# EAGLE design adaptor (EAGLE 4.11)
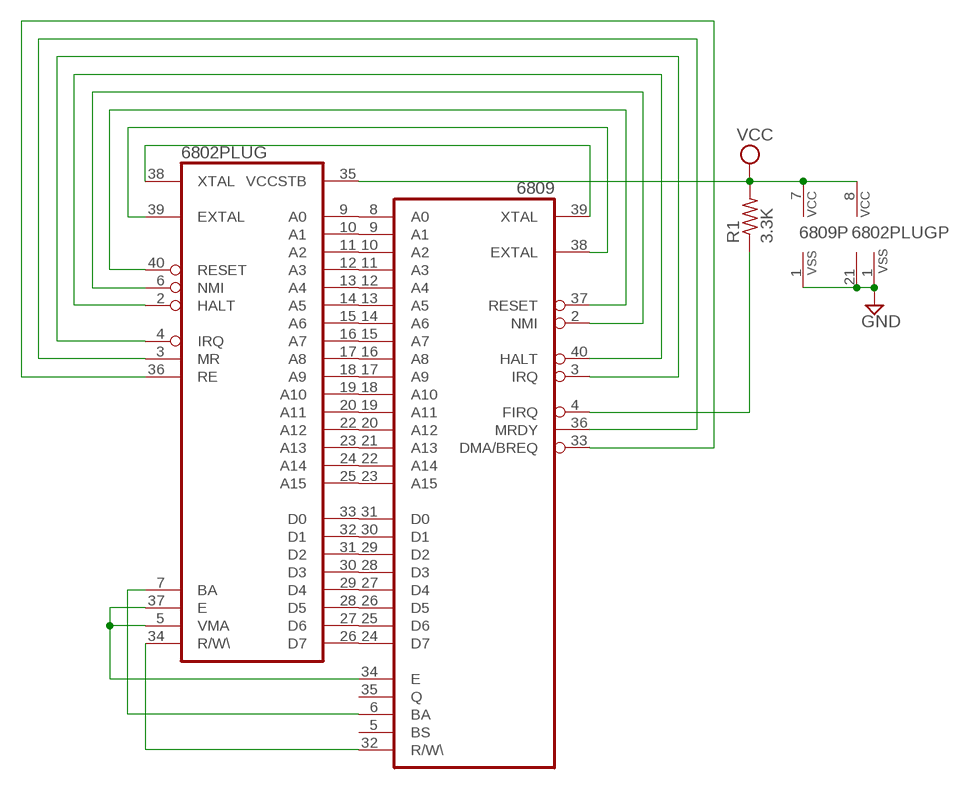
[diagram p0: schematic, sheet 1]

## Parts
6802PLUG  6802  [DIL40]
6809  6809  [DIL40]
R1  3.3K  R-US_0207/10  [0207/10]

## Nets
GND: 6802PLUG.1(VSS) 6802PLUG.21(VSS) 6809.1(VSS)
N$1: 6802PLUG.9(A0) 6809.8(A0)
N$2: 6802PLUG.10(A1) 6809.9(A1)
N$3: 6802PLUG.11(A2) 6809.10(A2)
N$4: 6802PLUG.12(A3) 6809.11(A3)
N$5: 6802PLUG.13(A4) 6809.12(A4)
N$6: 6802PLUG.14(A5) 6809.13(A5)
N$7: 6802PLUG.15(A6) 6809.14(A6)
N$8: 6802PLUG.16(A7) 6809.15(A7)
N$9: 6802PLUG.17(A8) 6809.16(A8)
N$10: 6802PLUG.18(A9) 6809.17(A9)
N$11: 6802PLUG.19(A10) 6809.18(A10)
N$12: 6802PLUG.20(A11) 6809.19(A11)
N$13: 6802PLUG.22(A12) 6809.20(A12)
N$14: 6802PLUG.23(A13) 6809.21(A13)
N$15: 6802PLUG.24(A14) 6809.22(A14)
N$16: 6802PLUG.25(A15) 6809.23(A15)
N$17: 6802PLUG.26(D7) 6809.24(D7)
N$18: 6802PLUG.27(D6) 6809.25(D6)
N$19: 6802PLUG.28(D5) 6809.26(D5)
N$20: 6802PLUG.29(D4) 6809.27(D4)
N$21: 6802PLUG.30(D3) 6809.28(D3)
N$22: 6802PLUG.31(D2) 6809.29(D2)
N$23: 6802PLUG.32(D1) 6809.30(D1)
N$24: 6802PLUG.33(D0) 6809.31(D0)
N$25: 6802PLUG.34(R/W\) 6809.32(R/W\)
N$26: 6802PLUG.7(BA) 6809.6(BA)
N$27: 6802PLUG.5(VMA) 6802PLUG.37(E) 6809.34(E)
N$28: 6802PLUG.38(XTAL) 6809.39(XTAL)
N$29: 6802PLUG.39(EXTAL) 6809.38(EXTAL)
N$30: 6802PLUG.40(RESET) 6809.37(RESET)
N$31: 6802PLUG.6(NMI) 6809.2(NMI)
N$32: 6802PLUG.2(HALT) 6809.40(HALT)
N$33: 6802PLUG.4(IRQ) 6809.3(IRQ)
N$34: 6802PLUG.3(MR) 6809.36(MRDY)
N$35: 6802PLUG.36(RE) 6809.33(DMA/BREQ)
N$36: 6809.4(FIRQ) R1.1
VCC: 6802PLUG.8(VCC) 6802PLUG.35(VCCSTB) 6809.7(VCC) R1.2
Unconnected: 6809.5(BS) 6809.35(Q)

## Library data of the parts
6802PLUG = micro-motorola:6802: MICROCONTROLLER/MEMORY DEVICE
6809 = micro-motorola:6809: MICROCONTROLLER/MEMORY DEVICE
R1 = rcl:R-US_: RESISTOR, American symbol

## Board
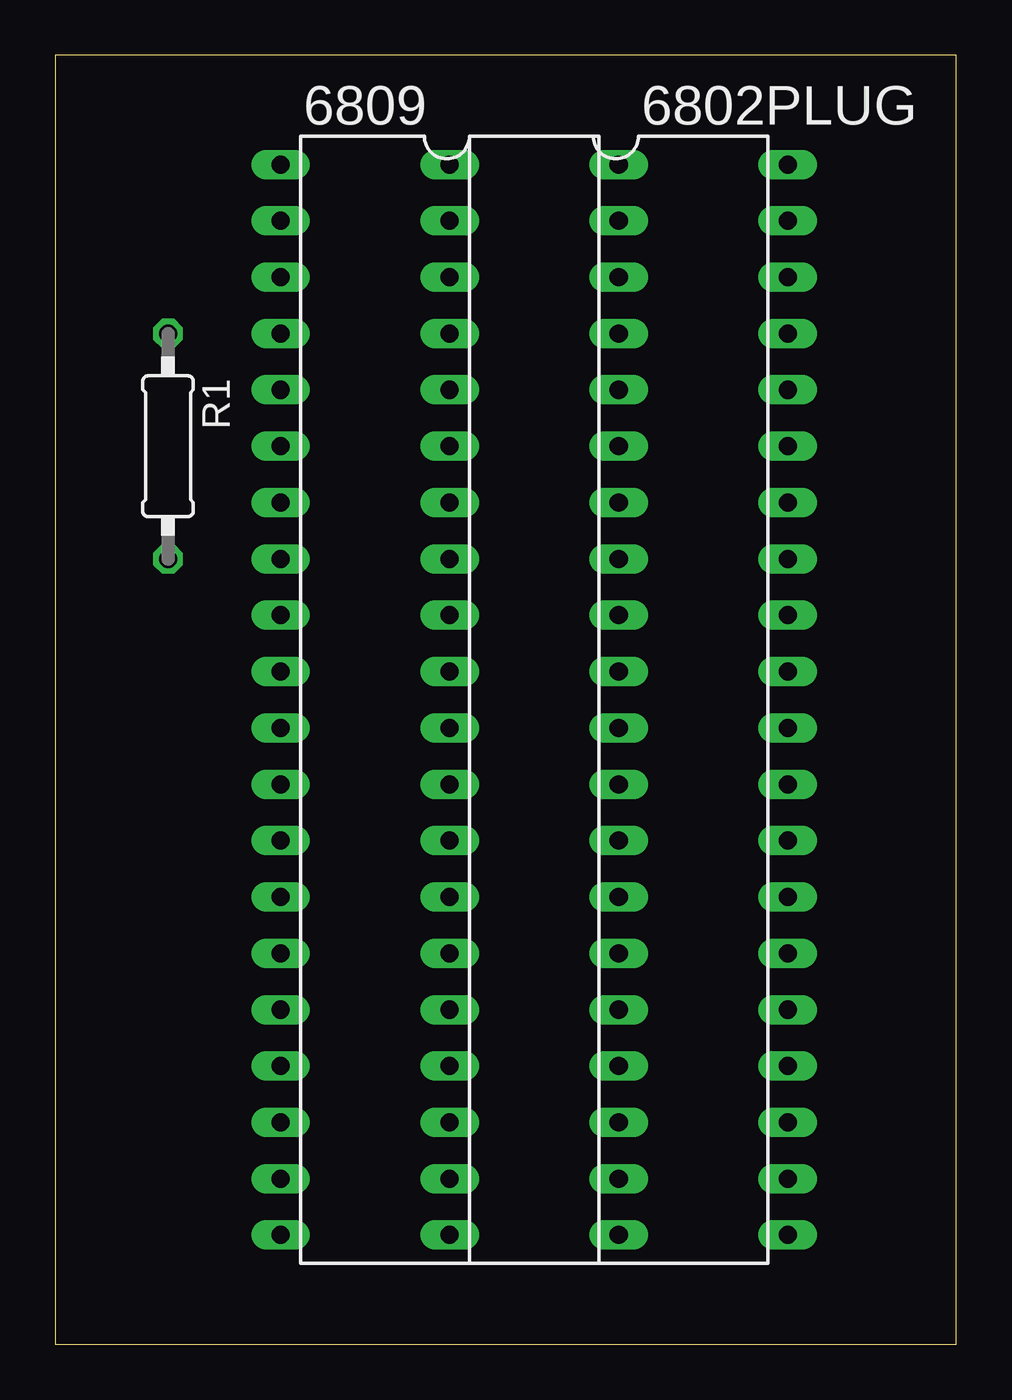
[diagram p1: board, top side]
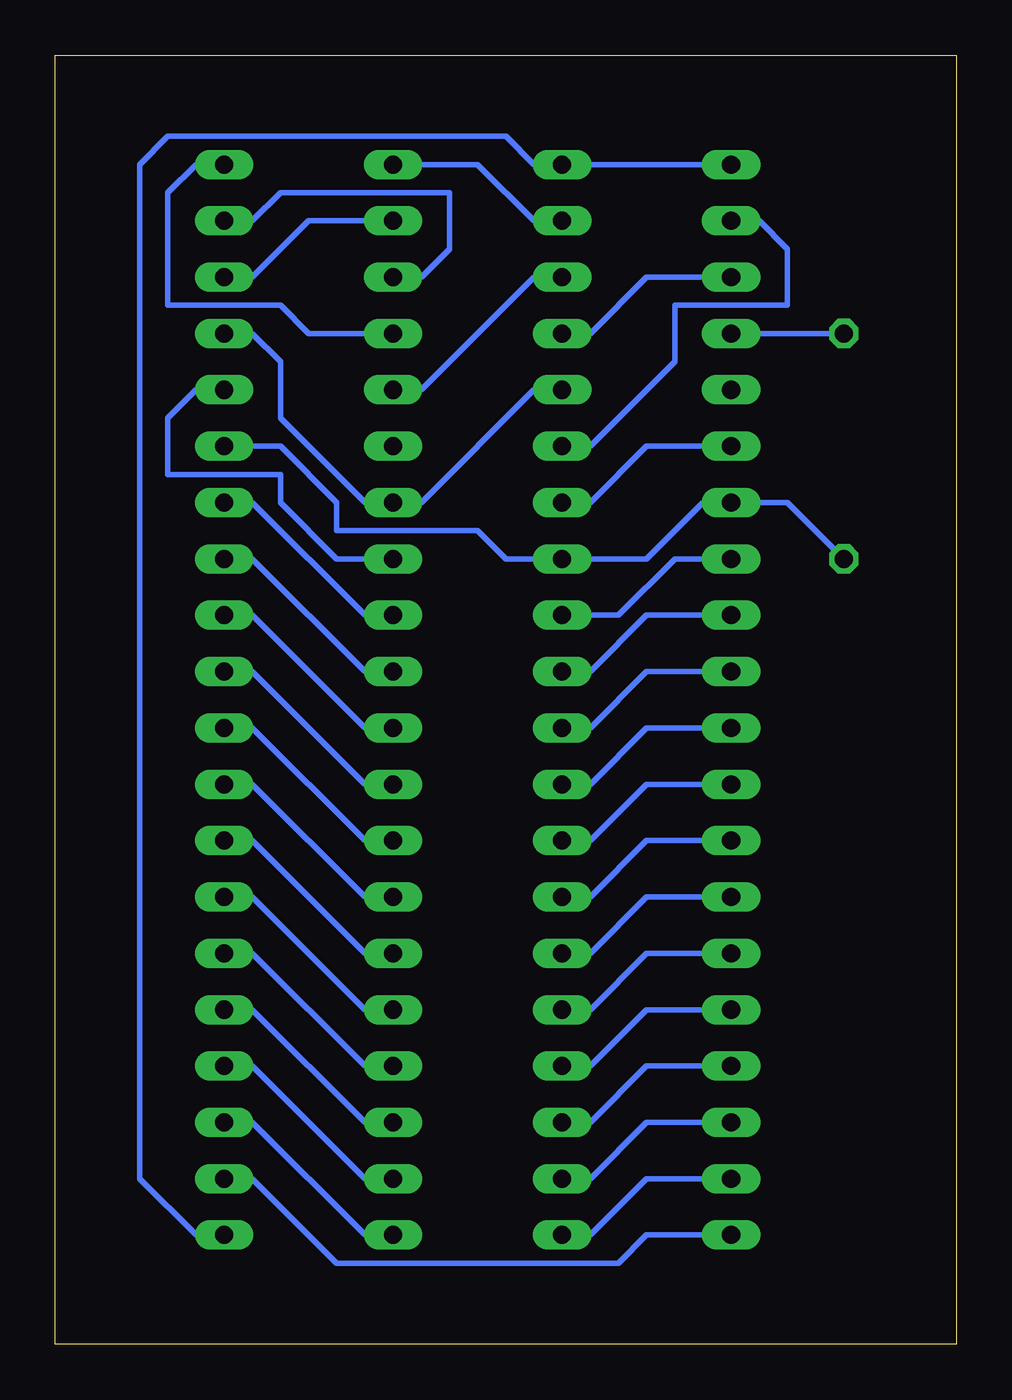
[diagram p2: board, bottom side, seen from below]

Size 40.62 x 58.09 mm. Coordinates in mm from the lower left corner, seen from the top.
Outline: 0,0 40.62,0 40.62,58.09 0,58.09 0,0
Copper layers (1*16): Top 0.035mm / dielectric 1.5mm / Bottom 0.035mm
Design rules "default": minimum track width 10mil, minimum drill 24mil, track to track 8mil, track to pad 8mil, pad to pad 8mil, via to via 8mil, smd to smd 8mil, copper to edge 40mil, drill to drill 8mil, minimum pad ring 10mil, minimum via ring 8mil, stop-mask expansion 4mil, vias tented up to drill 0mil, thermal gap 10mil

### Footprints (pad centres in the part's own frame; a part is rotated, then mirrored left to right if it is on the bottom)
DIL40 = drill 0.813 long: 1 -24.13,-7.62; 2 -21.59,-7.62; 3 -19.05,-7.62; 4 -16.51,-7.62; 5 -13.97,-7.62; 6 -11.43,-7.62; 7 -8.89,-7.62; 8 -6.35,-7.62; 9 -3.81,-7.62; 10 -1.27,-7.62; 11 1.27,-7.62; 12 3.81,-7.62; 13 6.35,-7.62; 14 8.89,-7.62; 15 11.43,-7.62; 16 13.97,-7.62; 17 16.51,-7.62; 18 19.05,-7.62; 19 21.59,-7.62; 20 24.13,-7.62; 21 24.13,7.62; 22 21.59,7.62; 23 19.05,7.62; 24 16.51,7.62; 25 13.97,7.62; 26 11.43,7.62; 27 8.89,7.62; 28 6.35,7.62; 29 3.81,7.62; 30 1.27,7.62; 31 -1.27,7.62; 32 -3.81,7.62; 33 -6.35,7.62; 34 -8.89,7.62; 35 -11.43,7.62; 36 -13.97,7.62; 37 -16.51,7.62; 38 -19.05,7.62; 39 -21.59,7.62; 40 -24.13,7.62
0207/10 = drill 0.813 octagon: 1 -5.08,0; 2 5.08,0

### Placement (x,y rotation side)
6802PLUG  25.39,29.05 270 top
6809  17.78,29.05 270 top
R1  5.08,40.48 270 top

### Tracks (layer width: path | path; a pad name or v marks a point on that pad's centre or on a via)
GND
  Bottom 0.254: 6802PLUG.21 34.28,4.92 36.82,7.46 36.82,53.18 35.55,54.45 20.32,54.45 19.05,53.18 6802PLUG.1 16.51,53.18 11.42,53.18 6809.1
N$1
  Bottom 0.254: 6809.8 11.42,35.4 12.69,35.4 15.23,32.86 16.51,32.86 6802PLUG.9
N$2
  Bottom 0.254: 6809.9 11.42,32.86 13.96,32.86 16.51,30.32 6802PLUG.10
N$3
  Bottom 0.254: 6809.10 11.42,30.32 13.96,30.32 16.51,27.78 6802PLUG.11
N$4
  Bottom 0.254: 6809.11 11.42,27.78 13.96,27.78 16.51,25.23 6802PLUG.12
N$5
  Bottom 0.254: 6809.12 11.42,25.23 13.96,25.23 16.51,22.7 6802PLUG.13
N$6
  Bottom 0.254: 6809.13 11.42,22.7 13.96,22.7 16.51,20.16 6802PLUG.14
N$7
  Bottom 0.254: 6809.14 11.42,20.16 13.96,20.16 16.51,17.62 6802PLUG.15
N$8
  Bottom 0.254: 6809.15 11.42,17.62 13.96,17.62 16.51,15.08 6802PLUG.16
N$9
  Bottom 0.254: 6809.16 11.42,15.08 13.96,15.08 16.51,12.54 6802PLUG.17
N$10
  Bottom 0.254: 6809.17 11.42,12.54 13.96,12.54 16.51,10 6802PLUG.18
N$11
  Bottom 0.254: 6809.18 11.42,10 13.96,10 16.51,7.46 6802PLUG.19
N$12
  Bottom 0.254: 6809.19 11.42,7.46 13.96,7.46 16.51,4.92 6802PLUG.20
N$13
  Bottom 0.254: 6809.20 11.42,4.92 13.96,4.92 15.23,3.65 27.94,3.65 31.75,7.46 6802PLUG.22
N$14
  Bottom 0.254: 6809.21 26.67,4.92 31.75,10 6802PLUG.23
N$15
  Bottom 0.254: 6809.22 26.67,7.46 31.75,12.54 6802PLUG.24
N$16
  Bottom 0.254: 6809.23 26.67,10 31.75,15.08 6802PLUG.25
N$17
  Bottom 0.254: 6809.24 26.67,12.54 31.75,17.62 6802PLUG.26
N$18
  Bottom 0.254: 6809.25 26.67,15.08 31.75,20.16 6802PLUG.27
N$19
  Bottom 0.254: 6809.26 26.67,17.62 31.75,22.7 6802PLUG.28
N$20
  Bottom 0.254: 6809.27 26.67,20.16 31.75,25.23 6802PLUG.29
N$21
  Bottom 0.254: 6809.28 26.67,22.7 31.75,27.78 6802PLUG.30
N$22
  Bottom 0.254: 6809.29 26.67,25.23 31.75,30.32 6802PLUG.31
N$23
  Bottom 0.254: 6809.30 26.67,27.78 31.75,32.86 6802PLUG.32
N$24
  Bottom 0.254: 6809.31 26.67,30.32 31.75,35.4 6802PLUG.33
N$25
  Bottom 0.254: 6809.32 26.67,32.86 31.75,37.94 6802PLUG.34
N$26
  Bottom 0.254: 6809.6 11.42,40.48 13.96,40.48 16.51,37.94 6802PLUG.7
N$27
  Bottom 0.254: 6802PLUG.37 31.75,45.55 30.48,44.29 30.48,41.74 26.67,37.94 6809.34 24.12,37.94 19.05,43.02 6802PLUG.5
N$28
  Bottom 0.254: 6809.39 26.67,50.63 29.21,50.63 31.75,48.09 6802PLUG.38
N$29
  Bottom 0.254: 6809.38 24.12,48.09 22.86,49.37 22.86,51.91 30.48,51.91 31.75,50.63 6802PLUG.39
N$30
  Bottom 0.254: 6809.37 26.67,45.55 29.21,45.55 30.48,46.83 35.55,46.83 35.55,51.91 34.28,53.18 6802PLUG.40
N$31
  Bottom 0.254: 6802PLUG.6 16.51,40.48 12.69,44.29 12.69,46.83 7.62,46.83 7.62,49.37 8.88,50.63 6809.2
N$32
  Bottom 0.254: 6802PLUG.2 19.05,50.63 21.59,53.18 24.12,53.18 6809.40
N$33
  Bottom 0.254: 6809.3 11.42,48.09 13.96,48.09 16.51,45.55 6802PLUG.4
N$34
  Bottom 0.254: 6802PLUG.3 19.05,48.09 24.12,43.02 6809.36
N$35
  Bottom 0.254: 6809.33 26.67,35.4 27.94,35.4 30.48,37.94 30.48,39.2 35.55,39.2 35.55,41.74 34.28,43.02 6802PLUG.36
N$36
  Bottom 0.254: R1.1 8.88,45.55 6809.4
VCC
  Bottom 0.254: R1.2 7.62,37.94 8.88,37.94 6809.7 11.42,37.94 12.69,36.66 13.96,35.4 16.51,35.4 6802PLUG.8 19.05,35.4 20.32,35.4 21.59,36.66 27.94,36.66 27.94,37.94 30.48,40.48 31.75,40.48 6802PLUG.35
